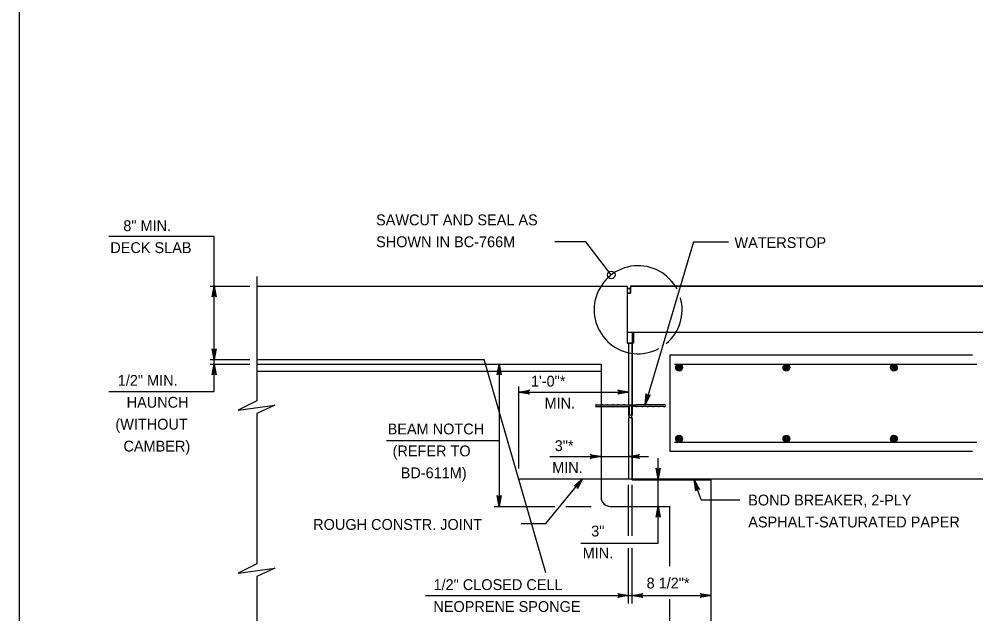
# Model space of a CAD drawing. Extents: x 636530 to 644067, y 294168 to 299122.
# Drawn here: x 639046.8 to 639311.9, y 296679.7 to 296844.4 of the extents above; entities that cross this region are included whole.
import ezdxf

# ---------------------------------------------------------------- set-up
doc = ezdxf.new("R2010")
doc.units = 0
doc.layers.add('1', color=7, linetype='Continuous')

msp = doc.modelspace()

# ---------------------------------------------------------------- linework, layer by layer
at = {"layer": '1'}
for p, q in [((639046.78, 297123.48), (639046.78, 296559.48)), ((639071.67, 296784.32), (639100.84, 296784.32)), ((639100.84, 296750.15), (639100.84, 296784.32)), ((639203.84, 296782.72), (639195.26, 296782.72)), ((639210.89, 296773.6), (639203.84, 296782.72)), ((639233.72, 296782.72), (639220.26, 296737.65)), ((639233.72, 296782.72), (639243.37, 296782.72)), ((639112.67, 296773.19), (639112.67, 296738.72)), ((639099.73, 296770.47), (639110.72, 296770.47)), ((639112.67, 296770.47), (639215.31, 296770.47)), ((639215.31, 296770.47), (639215.31, 296754.72)), ((639215.31, 296769.84), (639216.26, 296769.84)), ((639216.26, 296770.47), (639367.07, 296770.47)), ((639216.26, 296770.47), (639216.26, 296768.56)), ((639215.31, 296768.56), (639216.26, 296768.56)), ((639216.65, 296757.77), (639367.07, 296757.77)), ((639216.65, 296757.77), (639216.65, 296754.72)), ((639217.03, 296757.77), (639217.03, 296754.72)), ((639215.31, 296754.72), (639216.65, 296754.72)), ((639215.7, 296754.72), (639215.7, 296737.65)), ((639217.03, 296754.72), (639216.65, 296754.72)), ((639216.65, 296754.72), (639216.65, 296737.65)), ((639227.16, 296751.42), (639227.16, 296724.75)), ((639227.16, 296751.42), (639310.98, 296751.42)), ((639099.73, 296750.15), (639110.72, 296750.15)), ((639099.73, 296748.88), (639110.72, 296748.88)), ((639100.84, 296741.32), (639100.84, 296750.15)), ((639112.67, 296750.15), (639175.68, 296750.15)), ((639112.67, 296748.88), (639176.05, 296748.88)), ((639192.72, 296691.12), (639175.68, 296750.15)), ((639176.05, 296748.88), (639208.07, 296748.88)), ((639179.8, 296748.88), (639179.8, 296709.51)), ((639208.07, 296748.88), (639208.07, 296712.05)), ((639228.38, 296748.88), (639312.25, 296748.88)), ((639112.67, 296746.98), (639176.6, 296746.98)), ((639176.6, 296746.98), (639208.07, 296746.98)), ((639185.21, 296742.73), (639185.21, 296720.03)), ((639071.67, 296741.32), (639100.84, 296741.32)), ((639185.21, 296741.16), (639215.69, 296741.16)), ((639206.74, 296737.8), (639206.51, 296737.39)), ((639206.51, 296737.39), (639206.74, 296736.99)), ((639206.74, 296737.8), (639206.82, 296737.65)), ((639206.82, 296737.14), (639206.74, 296736.99)), ((639206.82, 296737.65), (639208.18, 296737.65)), ((639206.82, 296737.14), (639208.18, 296737.14)), ((639208.26, 296737.8), (639208.18, 296737.65)), ((639208.18, 296737.14), (639208.26, 296736.99)), ((639208.26, 296737.8), (639208.35, 296737.65)), ((639208.35, 296737.14), (639208.26, 296736.99)), ((639208.35, 296737.65), (639209.7, 296737.65)), ((639208.35, 296737.14), (639209.7, 296737.14)), ((639209.79, 296737.8), (639209.7, 296737.65)), ((639209.7, 296737.14), (639209.79, 296736.99)), ((639209.79, 296737.8), (639209.87, 296737.65)), ((639209.87, 296737.14), (639209.79, 296736.99)), ((639209.87, 296737.65), (639211.23, 296737.65)), ((639209.87, 296737.14), (639211.23, 296737.14)), ((639211.31, 296737.8), (639211.23, 296737.65)), ((639211.23, 296737.14), (639211.31, 296736.99)), ((639211.31, 296737.8), (639211.39, 296737.65)), ((639211.39, 296737.14), (639211.31, 296736.99)), ((639211.39, 296737.65), (639212.75, 296737.65)), ((639211.39, 296737.14), (639212.75, 296737.14)), ((639212.83, 296737.8), (639212.75, 296737.65)), ((639212.75, 296737.14), (639212.83, 296736.99)), ((639212.83, 296737.8), (639212.92, 296737.65)), ((639212.92, 296737.14), (639212.83, 296736.99)), ((639212.92, 296737.65), (639214.27, 296737.65)), ((639212.92, 296737.14), (639214.27, 296737.14)), ((639214.36, 296737.8), (639214.27, 296737.65)), ((639214.27, 296737.14), (639214.36, 296736.99)), ((639214.36, 296737.8), (639214.44, 296737.65)), ((639214.44, 296737.14), (639214.36, 296736.99)), ((639214.44, 296737.65), (639217.89, 296737.65)), ((639214.44, 296737.14), (639215.69, 296737.14)), ((639215.69, 296737.14), (639215.69, 296734.73)), ((639215.84, 296737.45), (639216.5, 296737.45)), ((639215.84, 296737.45), (639215.84, 296734.73)), ((639216.5, 296737.45), (639216.5, 296734.73)), ((639216.65, 296737.14), (639216.65, 296734.73)), ((639217.89, 296737.14), (639216.65, 296737.14)), ((639217.97, 296737.8), (639217.89, 296737.65)), ((639217.89, 296737.14), (639217.97, 296736.99)), ((639217.97, 296737.8), (639218.06, 296737.65)), ((639218.06, 296737.14), (639217.97, 296736.99)), ((639219.41, 296737.65), (639218.06, 296737.65)), ((639219.41, 296737.14), (639218.06, 296737.14)), ((639219.5, 296737.8), (639219.41, 296737.65)), ((639219.41, 296737.14), (639219.5, 296736.99)), ((639219.5, 296737.8), (639219.58, 296737.65)), ((639219.58, 296737.14), (639219.5, 296736.99)), ((639220.94, 296737.65), (639219.58, 296737.65)), ((639220.94, 296737.14), (639219.58, 296737.14)), ((639221.02, 296737.8), (639220.94, 296737.65)), ((639220.94, 296737.14), (639221.02, 296736.99)), ((639221.02, 296737.8), (639221.11, 296737.65)), ((639221.11, 296737.14), (639221.02, 296736.99)), ((639222.46, 296737.65), (639221.11, 296737.65)), ((639222.46, 296737.14), (639221.11, 296737.14)), ((639222.55, 296737.8), (639222.46, 296737.65)), ((639222.46, 296737.14), (639222.55, 296736.99)), ((639222.55, 296737.8), (639222.63, 296737.65)), ((639222.63, 296737.14), (639222.55, 296736.99)), ((639223.99, 296737.65), (639222.63, 296737.65)), ((639223.99, 296737.14), (639222.63, 296737.14)), ((639224.07, 296737.8), (639223.99, 296737.65)), ((639223.99, 296737.14), (639224.07, 296736.99)), ((639224.07, 296737.8), (639224.15, 296737.65)), ((639224.15, 296737.14), (639224.07, 296736.99)), ((639225.51, 296737.65), (639224.15, 296737.65)), ((639225.51, 296737.14), (639224.15, 296737.14)), ((639225.59, 296737.8), (639225.51, 296737.65)), ((639225.51, 296737.14), (639225.59, 296736.99)), ((639225.59, 296737.8), (639225.82, 296737.39)), ((639225.82, 296737.39), (639225.59, 296736.99)), ((639112.67, 296735.2), (639112.67, 296693.58)), ((639216.5, 296734.73), (639215.84, 296734.73)), ((639215.7, 296734.02), (639215.69, 296717.13)), ((639216.65, 296734.02), (639216.65, 296717.13)), ((639148.63, 296727.72), (639179.8, 296727.72)), ((639228.38, 296727.29), (639312.25, 296727.29)), ((639227.16, 296724.75), (639310.98, 296724.75)), ((639193.85, 296723.31), (639221.18, 296723.31)), ((639223.87, 296699.32), (639223.87, 296722.85)), ((639185.21, 296717.13), (639215.69, 296717.13)), ((639192.8, 296704.78), (639202.96, 296717.13)), ((639215.69, 296717.13), (639367.07, 296717.13)), ((639216.65, 296716.83), (639216.65, 296717.13)), ((639216.65, 296716.83), (639238.55, 296716.83)), ((639235.83, 296711.3), (639233.86, 296716.83)), ((639238.55, 296644.38), (639238.55, 296717.13)), ((639215.69, 296701.37), (639215.69, 296715.5)), ((639216.65, 296701.37), (639216.65, 296715.5)), ((639235.83, 296711.3), (639246.55, 296711.3)), ((639178.45, 296709.51), (639195.25, 296709.51)), ((639198.33, 296709.51), (639205.33, 296709.51)), ((639210.61, 296709.51), (639227.12, 296709.51)), ((639227.12, 296692.93), (639227.12, 296709.51)), ((639185.94, 296704.78), (639192.8, 296704.78)), ((639202.45, 296699.32), (639223.87, 296699.32)), ((639215.69, 296682.59), (639215.69, 296697.91)), ((639216.65, 296682.59), (639216.65, 296697.91)), ((639112.67, 296690.06), (639112.67, 296638.8)), ((639159.42, 296684.83), (639238.55, 296684.83)), ((639227.12, 296644.38), (639227.12, 296683.85))]:
    msp.add_line(p, q, dxfattribs=at)
for points in [[(639100.84, 296770.47), (639101.4, 296767.49), (639101.32, 296767.6), (639101.24, 296767.72), (639101.14, 296767.78), (639101.04, 296767.84), (639100.94, 296767.85), (639100.84, 296767.87), (639100.74, 296767.85), (639100.64, 296767.84), (639100.54, 296767.78), (639100.44, 296767.72), (639100.36, 296767.6), (639100.28, 296767.49), (639100.84, 296770.47), (639100.36, 296767.6), (639100.44, 296767.72), (639100.84, 296770.47), (639100.54, 296767.78), (639100.64, 296767.84), (639100.84, 296770.47), (639100.74, 296767.85), (639100.84, 296767.87), (639100.84, 296770.47), (639100.94, 296767.85), (639101.04, 296767.84), (639100.84, 296770.47), (639101.14, 296767.78), (639101.24, 296767.72), (639100.84, 296770.47), (639101.32, 296767.6)], [(639100.84, 296750.15), (639100.28, 296753.13), (639100.36, 296753.02), (639100.44, 296752.9), (639100.54, 296752.84), (639100.64, 296752.78), (639100.74, 296752.77), (639100.84, 296752.75), (639100.94, 296752.77), (639101.04, 296752.78), (639101.14, 296752.84), (639101.24, 296752.9), (639101.32, 296753.02), (639101.4, 296753.13), (639100.84, 296750.15), (639101.32, 296753.02), (639101.24, 296752.9), (639100.84, 296750.15), (639101.14, 296752.84), (639101.04, 296752.78), (639100.84, 296750.15), (639100.94, 296752.77), (639100.84, 296752.75), (639100.84, 296750.15), (639100.74, 296752.77), (639100.64, 296752.78), (639100.84, 296750.15), (639100.54, 296752.84), (639100.44, 296752.9), (639100.84, 296750.15), (639100.36, 296753.02)], [(639100.84, 296748.88), (639101.4, 296745.9), (639101.32, 296746.01), (639101.24, 296746.13), (639101.14, 296746.19), (639101.04, 296746.25), (639100.94, 296746.26), (639100.84, 296746.28), (639100.74, 296746.26), (639100.64, 296746.25), (639100.54, 296746.19), (639100.44, 296746.13), (639100.36, 296746.01), (639100.28, 296745.9), (639100.84, 296748.88), (639100.36, 296746.01), (639100.44, 296746.13), (639100.84, 296748.88), (639100.54, 296746.19), (639100.64, 296746.25), (639100.84, 296748.88), (639100.74, 296746.26), (639100.84, 296746.28), (639100.84, 296748.88), (639100.94, 296746.26), (639101.04, 296746.25), (639100.84, 296748.88), (639101.14, 296746.19), (639101.24, 296746.13), (639100.84, 296748.88), (639101.32, 296746.01)], [(639179.8, 296748.88), (639180.36, 296745.9), (639180.28, 296746.01), (639180.2, 296746.13), (639180.1, 296746.19), (639180, 296746.25), (639179.9, 296746.26), (639179.8, 296746.28), (639179.7, 296746.26), (639179.6, 296746.25), (639179.5, 296746.19), (639179.4, 296746.13), (639179.32, 296746.01), (639179.24, 296745.9), (639179.8, 296748.88), (639179.32, 296746.01), (639179.4, 296746.13), (639179.8, 296748.88), (639179.5, 296746.19), (639179.6, 296746.25), (639179.8, 296748.88), (639179.7, 296746.26), (639179.8, 296746.28), (639179.8, 296748.88), (639179.9, 296746.26), (639180, 296746.25), (639179.8, 296748.88), (639180.1, 296746.19), (639180.2, 296746.13), (639179.8, 296748.88), (639180.28, 296746.01)], [(639185.21, 296741.16), (639188.2, 296741.72), (639187.97, 296741.56), (639187.85, 296741.36), (639187.81, 296741.16), (639187.85, 296740.96), (639187.97, 296740.76), (639188.2, 296740.6), (639185.21, 296741.16), (639187.97, 296740.76), (639187.85, 296740.96), (639185.21, 296741.16), (639187.81, 296741.16), (639187.85, 296741.36), (639185.21, 296741.16), (639187.97, 296741.56)], [(639215.69, 296741.16), (639212.71, 296740.6), (639212.94, 296740.76), (639213.06, 296740.96), (639213.09, 296741.16), (639213.06, 296741.36), (639212.94, 296741.56), (639212.71, 296741.72), (639215.69, 296741.16), (639212.94, 296741.56), (639213.06, 296741.36), (639215.69, 296741.16), (639213.09, 296741.16), (639213.06, 296740.96), (639215.69, 296741.16), (639212.94, 296740.76)], [(639220.26, 296737.65), (639220.58, 296740.67), (639220.62, 296740.53), (639220.66, 296740.4), (639220.74, 296740.31), (639220.82, 296740.23), (639220.91, 296740.18), (639221, 296740.14), (639221.1, 296740.13), (639221.21, 296740.11), (639221.32, 296740.14), (639221.43, 296740.17), (639221.54, 296740.26), (639221.65, 296740.35), (639220.26, 296737.65), (639221.54, 296740.26), (639221.43, 296740.17), (639220.26, 296737.65), (639221.32, 296740.14), (639221.21, 296740.11), (639220.26, 296737.65), (639221.1, 296740.13), (639221, 296740.14), (639220.26, 296737.65), (639220.91, 296740.18), (639220.82, 296740.23), (639220.26, 296737.65), (639220.74, 296740.31), (639220.66, 296740.4), (639220.26, 296737.65), (639220.62, 296740.53)], [(639112.67, 296738.72), (639107.48, 296736.18), (639117.63, 296737.57), (639112.67, 296735.2)], [(639208.07, 296723.31), (639205.09, 296722.75), (639205.32, 296722.91), (639205.44, 296723.11), (639205.47, 296723.31), (639205.44, 296723.51), (639205.32, 296723.71), (639205.09, 296723.87), (639208.07, 296723.31), (639205.32, 296723.71), (639205.44, 296723.51), (639208.07, 296723.31), (639205.47, 296723.31), (639205.44, 296723.11), (639208.07, 296723.31), (639205.32, 296722.91)], [(639215.69, 296723.31), (639218.68, 296723.87), (639218.45, 296723.71), (639218.33, 296723.51), (639218.29, 296723.31), (639218.33, 296723.11), (639218.45, 296722.91), (639218.68, 296722.75), (639215.69, 296723.31), (639218.45, 296722.91), (639218.33, 296723.11), (639215.69, 296723.31), (639218.29, 296723.31), (639218.33, 296723.51), (639215.69, 296723.31), (639218.45, 296723.71)], [(639223.87, 296717.13), (639223.31, 296720.11), (639223.39, 296720), (639223.47, 296719.88), (639223.57, 296719.82), (639223.67, 296719.76), (639223.77, 296719.75), (639223.87, 296719.73), (639223.97, 296719.75), (639224.07, 296719.76), (639224.17, 296719.82), (639224.27, 296719.88), (639224.35, 296720), (639224.43, 296720.11), (639223.87, 296717.13), (639224.35, 296720), (639224.27, 296719.88), (639223.87, 296717.13), (639224.17, 296719.82), (639224.07, 296719.76), (639223.87, 296717.13), (639223.97, 296719.75), (639223.87, 296719.73), (639223.87, 296717.13), (639223.77, 296719.75), (639223.67, 296719.76), (639223.87, 296717.13), (639223.57, 296719.82), (639223.47, 296719.88), (639223.87, 296717.13), (639223.39, 296720)], [(639202.96, 296717.13), (639201.5, 296714.47), (639201.51, 296714.61), (639201.52, 296714.75), (639201.48, 296714.86), (639201.44, 296714.97), (639201.37, 296715.05), (639201.31, 296715.12), (639201.22, 296715.17), (639201.13, 296715.22), (639201.02, 296715.24), (639200.9, 296715.26), (639200.77, 296715.22), (639200.63, 296715.18), (639202.96, 296717.13), (639200.77, 296715.22), (639200.9, 296715.26), (639202.96, 296717.13), (639201.02, 296715.24), (639201.13, 296715.22), (639202.96, 296717.13), (639201.22, 296715.17), (639201.31, 296715.12), (639202.96, 296717.13), (639201.37, 296715.05), (639201.44, 296714.97), (639202.96, 296717.13), (639201.48, 296714.86), (639201.52, 296714.75), (639202.96, 296717.13), (639201.51, 296714.61)], [(639233.86, 296716.83), (639235.39, 296714.2), (639235.17, 296714.37), (639234.94, 296714.41), (639234.74, 296714.38), (639234.56, 296714.28), (639234.41, 296714.1), (639234.34, 296713.83), (639233.86, 296716.83), (639234.41, 296714.1), (639234.56, 296714.28), (639233.86, 296716.83), (639234.74, 296714.38), (639234.94, 296714.41), (639233.86, 296716.83), (639235.17, 296714.37)], [(639179.8, 296709.51), (639179.24, 296712.49), (639179.32, 296712.38), (639179.4, 296712.26), (639179.5, 296712.2), (639179.6, 296712.14), (639179.7, 296712.13), (639179.8, 296712.11), (639179.9, 296712.13), (639180, 296712.14), (639180.1, 296712.2), (639180.2, 296712.26), (639180.28, 296712.38), (639180.36, 296712.49), (639179.8, 296709.51), (639180.28, 296712.38), (639180.2, 296712.26), (639179.8, 296709.51), (639180.1, 296712.2), (639180, 296712.14), (639179.8, 296709.51), (639179.9, 296712.13), (639179.8, 296712.11), (639179.8, 296709.51), (639179.7, 296712.13), (639179.6, 296712.14), (639179.8, 296709.51), (639179.5, 296712.2), (639179.4, 296712.26), (639179.8, 296709.51), (639179.32, 296712.38)], [(639223.87, 296709.51), (639224.43, 296706.53), (639224.35, 296706.64), (639224.27, 296706.76), (639224.17, 296706.82), (639224.07, 296706.88), (639223.97, 296706.89), (639223.87, 296706.91), (639223.77, 296706.89), (639223.67, 296706.88), (639223.57, 296706.82), (639223.47, 296706.76), (639223.39, 296706.64), (639223.31, 296706.53), (639223.87, 296709.51), (639223.39, 296706.64), (639223.47, 296706.76), (639223.87, 296709.51), (639223.57, 296706.82), (639223.67, 296706.88), (639223.87, 296709.51), (639223.77, 296706.89), (639223.87, 296706.91), (639223.87, 296709.51), (639223.97, 296706.89), (639224.07, 296706.88), (639223.87, 296709.51), (639224.17, 296706.82), (639224.27, 296706.76), (639223.87, 296709.51), (639224.35, 296706.64)], [(639112.67, 296693.58), (639107.48, 296691.04), (639117.63, 296692.42), (639112.67, 296690.06)], [(639215.69, 296684.83), (639212.71, 296684.27), (639212.94, 296684.43), (639213.06, 296684.63), (639213.09, 296684.83), (639213.06, 296685.03), (639212.94, 296685.23), (639212.71, 296685.39), (639215.69, 296684.83), (639212.94, 296685.23), (639213.06, 296685.03), (639215.69, 296684.83), (639213.09, 296684.83), (639213.06, 296684.63), (639215.69, 296684.83), (639212.94, 296684.43)], [(639216.65, 296684.83), (639219.63, 296685.39), (639219.4, 296685.23), (639219.28, 296685.03), (639219.25, 296684.83), (639219.28, 296684.63), (639219.4, 296684.43), (639219.63, 296684.27), (639216.65, 296684.83), (639219.4, 296684.43), (639219.28, 296684.63), (639216.65, 296684.83), (639219.25, 296684.83), (639219.28, 296685.03), (639216.65, 296684.83), (639219.4, 296685.23)], [(639238.55, 296684.83), (639235.57, 296684.27), (639235.8, 296684.43), (639235.92, 296684.63), (639235.95, 296684.83), (639235.92, 296685.03), (639235.8, 296685.23), (639235.57, 296685.39), (639238.55, 296684.83), (639235.8, 296685.23), (639235.92, 296685.03), (639238.55, 296684.83), (639235.95, 296684.83), (639235.92, 296684.63), (639238.55, 296684.83), (639235.8, 296684.43)]]:
    msp.add_lwpolyline(points, dxfattribs=at)
for points in [[(639367.07, 296770.47), (639216.26, 296770.47), (639216.26, 296768.56), (639215.31, 296768.56), (639215.31, 296757.77), (639367.07, 296757.77)], [(639215.31, 296768.56), (639216.26, 296768.56), (639216.26, 296769.84), (639215.31, 296769.84)], [(639215.7, 296737.65), (639216.65, 296737.65), (639216.65, 296754.72), (639215.7, 296754.72)], [(639215.7, 296717.13), (639216.65, 296717.13), (639216.65, 296734.02), (639215.7, 296734.02)]]:
    msp.add_lwpolyline(points, close=True, dxfattribs=at)
for centre, radius in [((639210.89, 296773.6), 1.06), ((639229.7, 296747.93), 0.952), ((639229.7, 296747.93), 0.714), ((639229.7, 296747.93), 0.476), ((639229.7, 296747.93), 0.238), ((639259.46, 296747.93), 0.952), ((639259.46, 296747.93), 0.714), ((639259.46, 296747.93), 0.476), ((639259.46, 296747.93), 0.238), ((639289.22, 296747.93), 0.952), ((639289.22, 296747.93), 0.714), ((639289.22, 296747.93), 0.476), ((639289.22, 296747.93), 0.238), ((639229.7, 296728.24), 0.952), ((639259.46, 296728.24), 0.952), ((639289.22, 296728.24), 0.952), ((639229.7, 296728.24), 0.714), ((639229.7, 296728.24), 0.476), ((639229.7, 296728.24), 0.238), ((639259.46, 296728.24), 0.714), ((639259.46, 296728.24), 0.476), ((639259.46, 296728.24), 0.238), ((639289.22, 296728.24), 0.714), ((639289.22, 296728.24), 0.476), ((639289.22, 296728.24), 0.238)]:
    msp.add_circle(centre, radius, dxfattribs=at)
for centre, radius, start, end in [((639218.34, 296763.95), 12.19, 27.7986, 297.9843), ((639218.34, 296763.95), 12.19, 309.6082, 15.5672), ((639210.61, 296712.05), 2.54, 180, 270)]:
    msp.add_arc(centre, radius, start, end, dxfattribs=at)
msp.add_ellipse((639216.17, 296734.73), major_axis=(0, 0.641), ratio=0.75, start_param=1.570796, end_param=4.712389, dxfattribs=at)

# ---------------------------------------------------------------- texts
for s, p in [('SAWCUT AND SEAL AS', (639145.71, 296787.33)), ('SHOWN IN BC-766M', (639145.71, 296781.26)), ('WATERSTOP', (639245.04, 296781.04)), ('1\'-0"*', (639188.64, 296742.67)), ('MIN.', (639192.41, 296736.6)), ('BEAM NOTCH', (639148.92, 296729.43)), ('(REFER TO', (639150.29, 296723.36)), ('3"*', (639195.23, 296724.82)), ('MIN.', (639194.52, 296718.75)), ('BD-611M)', (639152.53, 296717.29)), ('BOND BREAKER, 2-PLY ', (639248.86, 296709.75)), ('ROUGH CONSTR. JOINT', (639128.28, 296703)), ('ASPHALT-SATURATED PAPER', (639248.86, 296703.68)), ('3"', (639205.34, 296701.17)), ('MIN.', (639202.97, 296695.09)), ('1/2" CLOSED CELL', (639161.64, 296686.34)), ('8 1/2"*', (639220.68, 296686.77)), ('NEOPRENE SPONGE', (639161.59, 296680.27))]:
    msp.add_text(s, height=3, dxfattribs=at).set_placement(p)
for s, p in [('8" MIN.', (639075.66, 296785.72)), ('DECK SLAB', (639072.05, 296779.64)), ('1/2" MIN.', (639074.12, 296742.89)), ('HAUNCH', (639076.58, 296736.82)), ('(WITHOUT', (639073.46, 296730.75)), ('CAMBER)', (639075.7, 296724.68))]:
    msp.add_text(s, height=3, rotation=360, dxfattribs=at).set_placement(p)

doc.saveas('drawing.dxf')
